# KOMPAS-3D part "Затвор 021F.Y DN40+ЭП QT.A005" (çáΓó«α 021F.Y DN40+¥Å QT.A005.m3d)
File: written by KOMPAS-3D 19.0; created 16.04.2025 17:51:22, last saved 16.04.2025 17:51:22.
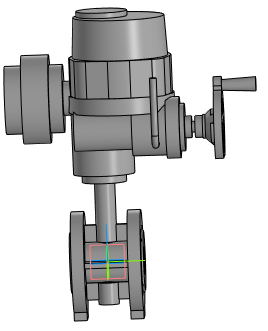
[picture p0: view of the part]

Document properties: Полное имя файла: Затвор 021F.Y DN40+ЭП QT.A005.a3d

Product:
- Part/product: Затвор 021F.Y DN40+ЭП QT.A005
    Масса: 42.9958

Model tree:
1. Операция без истории:1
